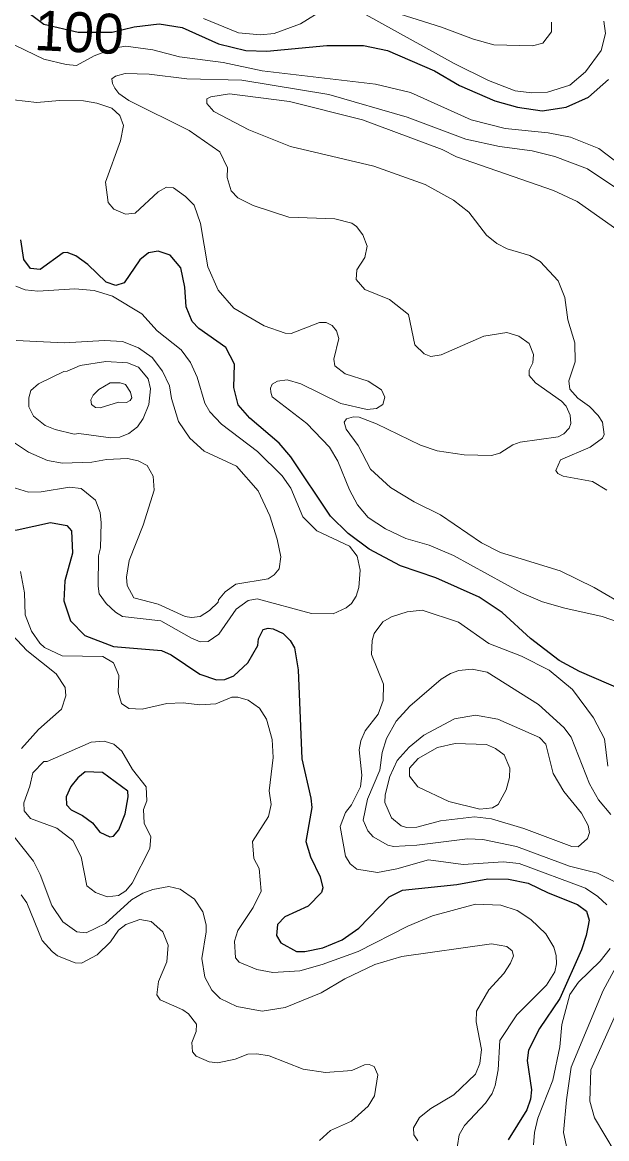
# Model space of a CAD drawing. Extents: x 673.6 to 698.9, y 7012 to 7040.1.
# Drawn here: x 680.243 to 681.414, y 7026.21 to 7028.448 of the extents above; entities that cross this region are included whole.
import ezdxf
from ezdxf.enums import TextEntityAlignment as Align

# ---------------------------------------------------------------- set-up
doc = ezdxf.new("R2010")
doc.units = 0
doc.header["$LTSCALE"] = 0.032
doc.layers.add('1', color=7, linetype='Continuous', lineweight=25)
doc.layers.add('2', color=7, linetype='Continuous', lineweight=13)
doc.layers.add('61', color=7, linetype='Continuous')

msp = doc.modelspace()

# ---------------------------------------------------------------- linework, layer by layer
at = {"layer": '1'}
for points in [[(680.2036, 7028.5079), (680.2862, 7028.445), (680.355, 7028.4286), (680.4229, 7028.4286), (680.4674, 7028.4394), (680.5175, 7028.4457), (680.5631, 7028.4383), (680.6358, 7028.4053), (680.6907, 7028.3923), (680.7328, 7028.3907), (680.8534, 7028.4023), (680.9265, 7028.4019), (680.9744, 7028.3922), (681.0685, 7028.3509), (681.1187, 7028.3217), (681.1897, 7028.2911), (681.2352, 7028.2785), (681.2842, 7028.2708), (681.3327, 7028.2783), (681.3771, 7028.2985), (681.4171, 7028.334)], [(680.3327, 7027.9871), (680.3252, 7027.9863), (680.2791, 7027.953), (680.2593, 7027.955), (680.2462, 7027.9729), (680.2402, 7028.0123)], [(681.5018, 7027.0857), (681.3595, 7027.1469), (681.3187, 7027.1693), (681.2613, 7027.2134), (681.2044, 7027.2654), (681.1581, 7027.2958), (681.0715, 7027.3348), (681.0004, 7027.3592), (680.9379, 7027.3925), (680.8958, 7027.4237), (680.8602, 7027.4583), (680.7812, 7027.5776), (680.7573, 7027.6048), (680.6986, 7027.6546), (680.6753, 7027.6818), (680.6667, 7027.7165), (680.6683, 7027.7633), (680.6506, 7027.7968), (680.5967, 7027.8346), (680.5836, 7027.8486), (680.5714, 7027.878), (680.5688, 7027.9177), (680.5607, 7027.9564), (680.5389, 7027.9817), (680.5154, 7027.9896), (680.4957, 7027.9862), (680.4782, 7027.9721), (680.4468, 7027.9261), (680.4304, 7027.9208), (680.4108, 7027.9275), (680.3746, 7027.9628), (680.3502, 7027.9806), (680.3327, 7027.9871)], [(680.2099, 7027.4302), (680.2324, 7027.4308), (680.2997, 7027.4455), (680.3324, 7027.4396), (680.3419, 7027.4291), (680.3437, 7027.3841)], [(680.3437, 7027.3841), (680.3282, 7027.329), (680.3265, 7027.2884), (680.3397, 7027.2485), (680.3683, 7027.2193), (680.426, 7027.197), (680.522, 7027.1892), (680.5414, 7027.1804), (680.5989, 7027.1414), (680.6322, 7027.1302), (680.6486, 7027.131), (680.6671, 7027.1382), (680.6951, 7027.1642), (680.715, 7027.1992), (680.7163, 7027.2126), (680.7254, 7027.2312), (680.7353, 7027.2342), (680.7459, 7027.2326), (680.7653, 7027.2229), (680.7797, 7027.2093), (680.7882, 7027.1947), (680.7956, 7027.1507), (680.8031, 7026.972), (680.8211, 7026.8934), (680.8227, 7026.8741), (680.8113, 7026.8063), (680.8202, 7026.7755), (680.84, 7026.7357), (680.8448, 7026.7136), (680.8422, 7026.7038), (680.8156, 7026.6768), (680.7689, 7026.6552), (680.7545, 7026.6401), (680.7522, 7026.6177), (680.7612, 7026.6028), (680.7924, 7026.5854), (680.809, 7026.5857), (680.845, 7026.5933), (680.8841, 7026.609), (680.9174, 7026.6324), (680.9777, 7026.6951), (681.0044, 7026.7085), (681.1137, 7026.7198), (681.1758, 7026.7315), (681.2172, 7026.7307), (681.2564, 7026.7226), (681.2965, 7026.7035), (681.355, 7026.68), (681.3732, 7026.6665), (681.3783, 7026.6485), (681.3758, 7026.6343), (681.3725, 7026.6177), (681.3634, 7026.5891), (681.3201, 7026.4912), (681.2794, 7026.4313), (681.2568, 7026.3876), (681.2542, 7026.3671), (681.2632, 7026.3087), (681.261, 7026.2894), (681.254, 7026.2686), (681.2165, 7026.2082)]]:
    msp.add_lwpolyline(points, dxfattribs=at)
msp.add_lwpolyline([(680.4036, 7026.9443), (680.3691, 7026.9458), (680.3542, 7026.9342), (680.3402, 7026.9164), (680.3312, 7026.8956), (680.3315, 7026.8795), (680.341, 7026.8699), (680.3639, 7026.8583), (680.3836, 7026.8436), (680.3981, 7026.8247), (680.4185, 7026.8155), (680.4258, 7026.8172), (680.4365, 7026.8295), (680.4493, 7026.8618), (680.4553, 7026.8958), (680.4542, 7026.9069)], close=True, dxfattribs=at)
at = {"layer": '2'}
for points in [[(680.6058, 7028.456), (680.6762, 7028.4277), (680.7203, 7028.4236), (680.7479, 7028.4262), (680.8001, 7028.4451), (680.8477, 7028.4745)], [(681.3034, 7028.4485), (681.3032, 7028.4295), (681.2856, 7028.4064), (681.2652, 7028.4014), (681.1875, 7028.4035), (681.1468, 7028.4144), (681.0827, 7028.439), (680.9997, 7028.465)], [(680.9317, 7028.4636), (681.1084, 7028.3662), (681.1768, 7028.332), (681.2307, 7028.3109), (681.2638, 7028.3069), (681.2949, 7028.3086), (681.34, 7028.3222), (681.3715, 7028.3493), (681.4026, 7028.3918), (681.4111, 7028.4261), (681.4081, 7028.4509)], [(681.4425, 7028.1615), (681.3977, 7028.1952), (681.3412, 7028.2179), (681.2965, 7028.2271), (681.2103, 7028.2354), (681.1421, 7028.253), (681.0208, 7028.3076), (680.9507, 7028.3242), (680.7237, 7028.351), (680.6453, 7028.3676), (680.5579, 7028.3792), (680.5043, 7028.3931), (680.4501, 7028.4005), (680.43, 7028.3972), (680.387, 7028.3814), (680.3518, 7028.3622), (680.3311, 7028.3636), (680.2864, 7028.3746), (680.1514, 7028.4391)], [(681.4577, 7027.2753), (681.3886, 7027.3152), (681.3207, 7027.3486), (681.2013, 7027.3859), (681.1628, 7027.4047), (681.0805, 7027.4614), (681.0279, 7027.4869), (680.9809, 7027.5161), (680.9404, 7027.5525), (680.9158, 7027.5998), (680.8919, 7027.633), (680.8878, 7027.6467), (680.8925, 7027.6537), (680.9068, 7027.6575), (680.918, 7027.6568), (680.9529, 7027.6436), (681.0405, 7027.6007), (681.0742, 7027.5895), (681.1285, 7027.5813), (681.1831, 7027.5798), (681.1999, 7027.5846), (681.2254, 7027.6015), (681.2404, 7027.6071), (681.3163, 7027.6176), (681.3276, 7027.6235), (681.3386, 7027.6351), (681.342, 7027.6442), (681.3406, 7027.6608), (681.3323, 7027.6788), (681.3235, 7027.6887), (681.2708, 7027.7259), (681.2587, 7027.7402), (681.2584, 7027.751), (681.2659, 7027.7661), (681.2674, 7027.7828), (681.2582, 7027.8048), (681.2377, 7027.8195), (681.2139, 7027.8269), (681.1676, 7027.8194), (681.0821, 7027.7817), (681.0614, 7027.7785), (681.0482, 7027.7841), (681.0297, 7027.8022), (681.0166, 7027.8624), (680.9786, 7027.8928), (680.9295, 7027.9128), (680.9121, 7027.9329), (680.9131, 7027.952), (680.9291, 7027.977), (680.9337, 7027.9995), (680.9255, 7028.0225), (680.9128, 7028.0393), (680.9034, 7028.0458), (680.8692, 7028.0545), (680.777, 7028.0577), (680.7054, 7028.0811), (680.6747, 7028.0967), (680.6614, 7028.1105), (680.6536, 7028.1373), (680.6542, 7028.1566), (680.639, 7028.1889), (680.577, 7028.2314), (680.4566, 7028.2916), (680.4367, 7028.306), (680.4283, 7028.3162), (680.4234, 7028.3261), (680.4226, 7028.3351), (680.43, 7028.3406), (680.4489, 7028.3456), (680.4974, 7028.3445), (680.5727, 7028.3349), (680.6831, 7028.3323), (680.857, 7028.3036), (681.0141, 7028.2581), (681.1315, 7028.2145), (681.1988, 7028.1993), (681.2646, 7028.191), (681.3096, 7028.1793), (681.375, 7028.1548), (681.4743, 7028.0887)], [(680.2255, 7028.2929), (680.2719, 7028.288), (680.3175, 7028.292), (680.3659, 7028.2912), (680.3922, 7028.2863), (680.4221, 7028.2762), (680.4384, 7028.2617), (680.4456, 7028.2415), (680.4397, 7028.2112), (680.4095, 7028.1277), (680.4149, 7028.0872), (680.4267, 7028.0742), (680.4496, 7028.0641), (680.469, 7028.0661), (680.5152, 7028.1086), (680.5319, 7028.1177), (680.5457, 7028.1168), (680.57, 7028.0995)], [(681.4385, 7028.0295), (681.3543, 7028.0895), (681.307, 7028.1116), (681.1131, 7028.179), (681.0838, 7028.1936), (680.9248, 7028.2531), (680.7781, 7028.2897), (680.6584, 7028.3052), (680.6207, 7028.2994), (680.6125, 7028.2948), (680.6125, 7028.2859), (680.6265, 7028.2698), (680.6969, 7028.2326), (680.7801, 7028.1993), (680.9474, 7028.1598), (681.0499, 7028.1235), (681.1068, 7028.0917), (681.1378, 7028.0677), (681.1729, 7028.0216), (681.1935, 7028.0049), (681.2146, 7027.9944), (681.2596, 7027.9808), (681.2803, 7027.9687), (681.3162, 7027.9302), (681.33, 7027.897), (681.3362, 7027.8523), (681.3502, 7027.806), (681.3503, 7027.7679)], [(680.57, 7028.0995), (680.5876, 7028.0817), (680.5998, 7028.0451), (680.6148, 7027.9584), (680.6353, 7027.9114), (680.6665, 7027.8755)], [(680.2207, 7027.5175), (680.2555, 7027.5065), (680.2807, 7027.5073), (680.3376, 7027.5164), (680.3609, 7027.5138), (680.3895, 7027.4908), (680.3987, 7027.4657), (680.4013, 7027.4453), (680.3995, 7027.3948), (680.3956, 7027.3786), (680.3947, 7027.3181), (680.3973, 7027.3027), (680.4107, 7027.2835), (680.4296, 7027.2658), (680.4436, 7027.2575), (680.5204, 7027.2484), (680.5818, 7027.2136), (680.5994, 7027.2066), (680.6155, 7027.2074), (680.6367, 7027.2219), (680.6712, 7027.2719), (680.6954, 7027.2896), (680.7133, 7027.2926), (680.8225, 7027.2633), (680.8655, 7027.2625), (680.8915, 7027.2746), (680.9024, 7027.2831), (680.9117, 7027.2982), (680.9172, 7027.3155), (680.9197, 7027.3503), (680.9138, 7027.3783), (680.8984, 7027.3983), (680.833, 7027.4291), (680.8048, 7027.4568), (680.7808, 7027.5147), (680.7636, 7027.5393), (680.7143, 7027.5878), (680.6422, 7027.6427), (680.6184, 7027.6673), (680.6087, 7027.6851), (680.5934, 7027.7368), (680.5798, 7027.7666), (680.561, 7027.7921), (680.5134, 7027.8298), (680.4826, 7027.8639), (680.4234, 7027.8992), (680.3872, 7027.9107), (680.3484, 7027.9141), (680.2744, 7027.9092), (680.2489, 7027.9125), (680.2302, 7027.9194)], [(680.6665, 7027.8755), (680.7274, 7027.84), (680.7697, 7027.8253), (680.7816, 7027.8245), (680.8385, 7027.8465), (680.852, 7027.8466), (680.8639, 7027.8407), (680.8722, 7027.8298), (680.877, 7027.8149), (680.8672, 7027.773), (680.8689, 7027.7599), (680.8899, 7027.7441), (680.9362, 7027.7291), (680.9628, 7027.7114), (680.969, 7027.6971), (680.9655, 7027.6822), (680.9529, 7027.674), (680.9342, 7027.6725), (680.881, 7027.6846), (680.8008, 7027.7237), (680.7738, 7027.7315), (680.7541, 7027.7291), (680.7436, 7027.7232), (680.7399, 7027.7153), (680.7406, 7027.7067), (680.7433, 7027.698), (680.8129, 7027.6445), (680.8587, 7027.5971), (680.8754, 7027.5689), (680.8985, 7027.5111), (680.9145, 7027.4812), (680.9356, 7027.4561), (680.9705, 7027.4328), (681.0115, 7027.4138), (681.0578, 7027.4004), (681.1071, 7027.3799), (681.2432, 7027.3045), (681.2851, 7027.2869), (681.3297, 7027.2738), (681.4046, 7027.2574), (681.5045, 7027.2223)], [(680.2308, 7027.8106), (680.327, 7027.8057), (680.4079, 7027.8105), (680.4439, 7027.8088), (680.476, 7027.7957), (680.5034, 7027.7766), (680.5238, 7027.7494), (680.5377, 7027.7198), (680.5417, 7027.6942), (680.5556, 7027.6483), (680.5788, 7027.615), (680.6074, 7027.5887), (680.6722, 7027.5586), (680.7152, 7027.5093), (680.7386, 7027.4594), (680.7539, 7027.4122), (680.7611, 7027.3766), (680.7577, 7027.353), (680.7476, 7027.3409), (680.7356, 7027.3331)], [(681.3503, 7027.7679), (681.3381, 7027.73), (681.3402, 7027.713), (681.3559, 7027.6949), (681.3794, 7027.678), (681.3969, 7027.6604)], [(681.3969, 7027.6604), (681.4054, 7027.6466), (681.4086, 7027.6224), (681.4052, 7027.6148), (681.3809, 7027.5966), (681.321, 7027.5715), (681.3119, 7027.5499), (681.3157, 7027.5439), (681.3262, 7027.5386), (681.3852, 7027.5277), (681.4137, 7027.5106)], [(680.6182, 7027.2696), (680.5993, 7027.2576), (680.5817, 7027.2551), (680.5693, 7027.2572), (680.5149, 7027.282), (680.4666, 7027.2949), (680.4533, 7027.3196), (680.4517, 7027.3361), (680.457, 7027.3697), (680.4849, 7027.4404), (680.5071, 7027.5108), (680.5049, 7027.5387), (680.4929, 7027.56), (680.4754, 7027.5692), (680.4538, 7027.5739), (680.4119, 7027.5722), (680.3823, 7027.5665), (680.3236, 7027.5644), (680.2933, 7027.5699), (680.2553, 7027.5865), (680.1666, 7027.6454)], [(681.1113, 7026.1757), (681.118, 7026.2182), (681.1289, 7026.2366), (681.171, 7026.2818), (681.184, 7026.3012), (681.1902, 7026.3169), (681.1965, 7026.3488), (681.1998, 7026.4075), (681.2337, 7026.4587), (681.2934, 7026.5185), (681.3101, 7026.5451), (681.3133, 7026.5607), (681.3125, 7026.5779), (681.3076, 7026.5943), (681.2918, 7026.6209), (681.2618, 7026.6499), (681.2346, 7026.6677), (681.2015, 7026.6788), (681.1512, 7026.6805), (681.0649, 7026.6571), (681.0151, 7026.6362), (680.9161, 7026.586), (680.8434, 7026.5596), (680.7987, 7026.5472), (680.7448, 7026.5434), (680.7131, 7026.5495), (680.6772, 7026.5643), (680.67, 7026.5732), (680.6684, 7026.6062), (680.6746, 7026.6281), (680.7057, 7026.6739), (680.7218, 7026.7068), (680.7177, 7026.7524), (680.707, 7026.7721), (680.7045, 7026.8065), (680.7359, 7026.8561), (680.7414, 7026.8807), (680.7373, 7026.9076), (680.7455, 7026.9749), (680.7439, 7027.0105), (680.7324, 7027.0512), (680.7181, 7027.0736), (680.6955, 7027.0893), (680.6749, 7027.0956), (680.6629, 7027.0957), (680.6308, 7027.0819), (680.5986, 7027.0801), (680.5655, 7027.0841), (680.5328, 7027.0832), (680.4833, 7027.0714), (680.4561, 7027.0727), (680.442, 7027.0828), (680.4349, 7027.1058), (680.4365, 7027.1388), (680.4254, 7027.1641), (680.4046, 7027.1769), (680.3227, 7027.1783), (680.2876, 7027.195), (680.2779, 7027.2037), (680.2616, 7027.228), (680.249, 7027.2606), (680.2475, 7027.3047), (680.2391, 7027.3473)], [(680.7356, 7027.3331), (680.6711, 7027.322), (680.6495, 7027.3068), (680.6358, 7027.2907), (680.6351, 7027.2859), (680.6182, 7027.2696)], [(681.4142, 7026.6792), (681.3963, 7026.6962), (681.3711, 7026.7128), (681.2383, 7026.762), (681.2063, 7026.7653), (681.1265, 7026.7604), (681.0566, 7026.7693), (680.9936, 7026.7512), (680.9546, 7026.744), (680.9131, 7026.7507), (680.8997, 7026.7617), (680.8902, 7026.7768), (680.8796, 7026.8366), (680.8903, 7026.8641), (680.9022, 7026.88), (680.9207, 7026.9155), (680.923, 7026.9394), (680.9181, 7026.9898), (680.9211, 7027.0079), (680.9298, 7027.0284), (680.9561, 7027.0614), (680.9657, 7027.0891), (680.9665, 7027.1219), (680.9428, 7027.1811), (680.9437, 7027.2095), (680.9476, 7027.2235), (680.9655, 7027.2465), (680.9824, 7027.2563), (681.0141, 7027.2667), (681.0443, 7027.2698), (681.117, 7027.2457), (681.1775, 7027.2034), (681.2432, 7027.1779), (681.2988, 7027.1494), (681.3454, 7027.1112), (681.3874, 7027.054), (681.4094, 7027.0123), (681.4162, 7026.9572)], [(680.2129, 7027.2314), (680.2519, 7027.1891), (680.3111, 7027.1422), (680.3291, 7027.1147), (680.3304, 7027.0983), (680.3214, 7027.0718), (680.2755, 7027.0307), (680.2415, 7026.9929)], [(681.1743, 7027.1454), (681.144, 7027.1515), (681.1174, 7027.1491), (681.1008, 7027.1432), (681.0822, 7027.1315), (681.0194, 7027.0778), (680.9918, 7027.0477), (680.9728, 7027.0128), (680.9639, 7026.9845), (680.9591, 7026.949), (680.9343, 7026.8911), (680.9257, 7026.8492), (680.9351, 7026.8276), (680.9459, 7026.8154), (680.9756, 7026.799), (680.9868, 7026.7965), (681.0335, 7026.799), (681.1346, 7026.8113), (681.1656, 7026.8105), (681.2328, 7026.7962), (681.3393, 7026.7566), (681.3951, 7026.7429), (681.45, 7026.7155)], [(681.3796, 7026.922), (681.3426, 7027.0157), (681.3281, 7027.0348), (681.2774, 7027.0809), (681.1743, 7027.1454)], [(681.4221, 7026.8603), (681.3974, 7026.8895), (681.3796, 7026.922)], [(680.2085, 7026.8386), (680.2656, 7026.7669), (680.2791, 7026.74), (680.302, 7026.6778), (680.3242, 7026.645), (680.3521, 7026.6251), (680.3711, 7026.6231), (680.4095, 7026.6418), (680.4616, 7026.6892), (680.4844, 7026.7029), (680.5043, 7026.7101), (680.5365, 7026.7158), (680.5593, 7026.7104), (680.5878, 7026.6904), (680.6047, 7026.6651), (680.6114, 7026.6394), (680.6116, 7026.6251), (680.6026, 7026.5717), (680.6084, 7026.534), (680.6227, 7026.5083), (680.6392, 7026.4913), (680.6729, 7026.4752), (680.7235, 7026.4663), (680.7699, 7026.4736), (680.8416, 7026.5026), (680.8892, 7026.5306), (680.949, 7026.5594), (681.0035, 7026.5758), (681.1827, 7026.6009), (681.2136, 7026.596), (681.2242, 7026.5873), (681.2273, 7026.5773), (681.2212, 7026.5621), (681.2074, 7026.5418), (681.1777, 7026.5091), (681.1532, 7026.4662), (681.1524, 7026.4448), (681.1631, 7026.389), (681.1597, 7026.361), (681.1511, 7026.3396), (681.1077, 7026.2983), (681.0614, 7026.2707), (681.0387, 7026.2531), (681.0266, 7026.2324), (681.0275, 7026.2182), (681.0357, 7026.2059)], [(680.8383, 7026.2069), (680.8607, 7026.2268), (680.9023, 7026.2455), (680.9358, 7026.2757), (680.9483, 7026.2965), (680.955, 7026.3382), (680.9482, 7026.3553), (680.9381, 7026.3592), (680.9287, 7026.3585), (680.9033, 7026.347), (680.8501, 7026.3429), (680.806, 7026.3495), (680.7376, 7026.3764), (680.7127, 7026.3806), (680.6946, 7026.3798), (680.6694, 7026.3702), (680.6345, 7026.3627), (680.6175, 7026.3644), (680.5912, 7026.3759), (680.5843, 7026.3846), (680.5828, 7026.4031), (680.5914, 7026.4252), (680.5923, 7026.4402), (680.576, 7026.4605), (680.5647, 7026.4685), (680.5194, 7026.4886), (680.5123, 7026.499), (680.5157, 7026.5254), (680.5327, 7026.5648), (680.5351, 7026.5981), (680.5243, 7026.6249), (680.5011, 7026.646), (680.4787, 7026.6502), (680.4501, 7026.64), (680.4358, 7026.6288), (680.4196, 7026.6053), (680.3933, 7026.579), (680.3616, 7026.5624), (680.3492, 7026.5633), (680.3133, 7026.5772), (680.3026, 7026.586), (680.2831, 7026.6076), (680.2524, 7026.6834), (680.241, 7026.6995)], [(681.2674, 7026.1979), (681.269, 7026.223), (681.2758, 7026.2515), (681.3059, 7026.3278), (681.3198, 7026.3948), (681.324, 7026.4395), (681.3402, 7026.4996), (681.3575, 7026.5242), (681.4004, 7026.5663), (681.4208, 7026.5915)], [(681.4366, 7026.5631), (681.4064, 7026.5076), (681.3428, 7026.3539), (681.333, 7026.2886), (681.3274, 7026.2226), (681.3347, 7026.1888)], [(681.4305, 7026.1829), (681.3891, 7026.2522), (681.38, 7026.2854), (681.3817, 7026.3483), (681.4373, 7026.4724)]]:
    msp.add_lwpolyline(points, dxfattribs=at)
for points in [[(680.326, 7027.7487), (680.3327, 7027.7489), (680.3588, 7027.7606), (680.4104, 7027.7686), (680.454, 7027.7655), (680.476, 7027.7569), (680.4954, 7027.7337), (680.4999, 7027.7138), (680.4964, 7027.682), (680.485, 7027.6545), (680.4741, 7027.6377), (680.4566, 7027.6241), (680.4385, 7027.6167), (680.4207, 7027.6158), (680.3561, 7027.6239), (680.3471, 7027.6225), (680.3087, 7027.6321), (680.2889, 7027.6405), (680.2657, 7027.6588), (680.2559, 7027.6778), (680.2559, 7027.6958), (680.2599, 7027.7102), (680.2758, 7027.7236)], [(680.4626, 7027.6959), (680.4595, 7027.7071), (680.4496, 7027.7225), (680.4391, 7027.7259), (680.4193, 7027.7259), (680.3966, 7027.7121), (680.3851, 7027.7007), (680.3806, 7027.6917), (680.3814, 7027.682), (680.3896, 7027.676), (680.3992, 7027.6758), (680.4354, 7027.6871), (680.4518, 7027.6865), (680.4594, 7027.6902)], [(681.1956, 7027.0513), (681.1508, 7027.0594), (681.1087, 7027.0522), (681.0474, 7027.0196), (681.0183, 7026.9953), (680.9942, 7026.9688), (680.9791, 7026.9365), (680.9698, 7026.8997), (680.9691, 7026.8847), (680.9825, 7026.8538), (681.0018, 7026.8377), (681.0129, 7026.8343), (681.0334, 7026.8351), (681.0808, 7026.8474), (681.1489, 7026.8556), (681.1831, 7026.8515), (681.2478, 7026.8321), (681.3441, 7026.7964), (681.3563, 7026.7953), (681.3753, 7026.812), (681.3792, 7026.8242), (681.3765, 7026.8381), (681.3631, 7026.8628), (681.3277, 7026.9066), (681.3062, 7026.9424), (681.2918, 7027.0012), (681.2794, 7027.015)], [(680.3609, 7026.7757), (680.3445, 7026.808), (680.3119, 7026.8332), (680.2596, 7026.8522), (680.247, 7026.8678), (680.246, 7026.8839), (680.2584, 7026.9171), (680.264, 7026.9441), (680.286, 7026.9663), (680.2929, 7026.9667), (680.3807, 7027.0052), (680.4067, 7027.0077), (680.4266, 7027.0011), (680.4421, 7026.9874), (680.4637, 7026.9505), (680.4909, 7026.9161), (680.4925, 7026.8876), (680.4859, 7026.8704), (680.487, 7026.8427), (680.5006, 7026.8159), (680.4982, 7026.7922), (680.463, 7026.7228), (680.4503, 7026.7075), (680.436, 7026.698), (680.413, 7026.6952), (680.3897, 7026.7037), (680.3725, 7026.7171)], [(681.173, 7027.0009), (681.1909, 7026.9928), (681.208, 7026.9797), (681.2196, 7026.953), (681.2188, 7026.9346), (681.2122, 7026.9096), (681.1965, 7026.8804), (681.1849, 7026.8738), (681.1594, 7026.8713), (681.0974, 7026.8866), (681.0351, 7026.9155), (681.0189, 7026.9375), (681.0188, 7026.9533), (681.0359, 7026.9725), (681.0747, 7026.9945), (681.1104, 7027.0027)]]:
    msp.add_lwpolyline(points, close=True, dxfattribs=at)

# ---------------------------------------------------------------- texts
at = {"layer": '61'}
msp.add_text('100', height=0.08, rotation=357.153, dxfattribs=at).set_placement((680.3549, 7028.3887), align=Align.CENTER)

doc.saveas('drawing.dxf')
